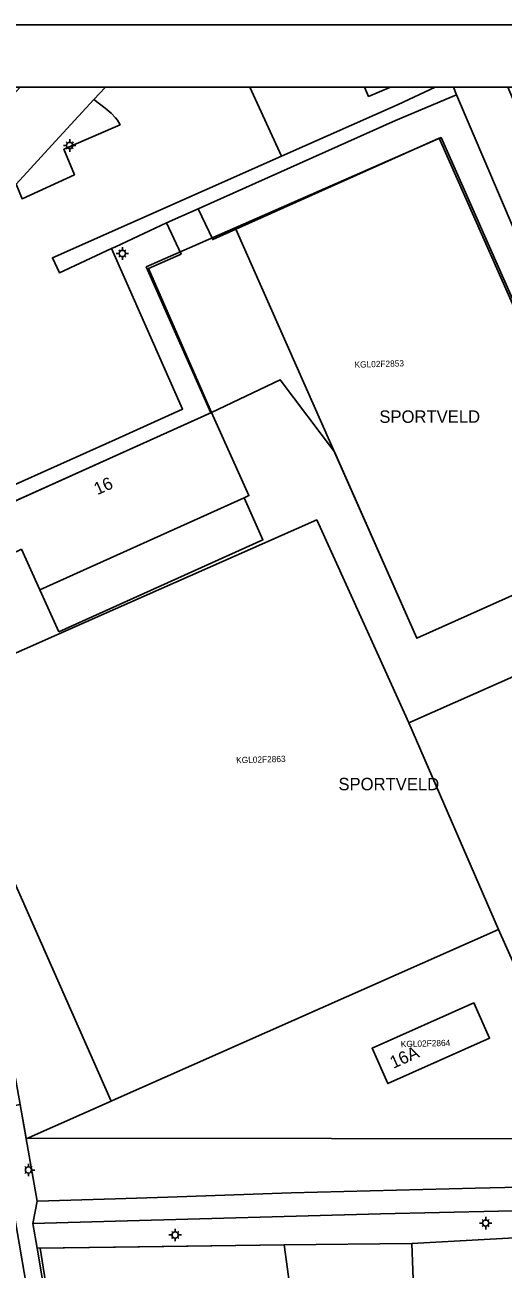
# Model space of a CAD drawing. Extents: x 124901 to 125496, y 515369 to 515789.
# Drawn here: x 124992.7 to 125031.2, y 515689 to 515789 of the extents above; entities that cross this region are included whole.
import ezdxf

# ---------------------------------------------------------------- set-up
doc = ezdxf.new("R2010")
doc.units = 0
for name, color, linetype in [('Alg Kaders', 7, 'Continuous'), ('Gebouw', 7, 'Continuous'), ('Lichtmast', 7, 'Continuous'), ('Luifel', 7, 'Continuous'), ('Onbegroeid terrein', 7, 'Continuous'), ('Parkeren', 7, 'Continuous'), ('Perceelnummers', 7, 'Continuous'), ('Perceelsgrenzen', 7, 'Continuous'), ('Scheiding', 7, 'Continuous'), ('Teksten', 7, 'Continuous'), ('Vegetatie', 7, 'Continuous'), ('Voetpad', 7, 'Continuous'), ('Wegen lokale weg', 7, 'Continuous')]:
    doc.layers.add(name, color=color, linetype=linetype)

msp = doc.modelspace()

# ---------------------------------------------------------------- linework, layer by layer
at = {"layer": 'Alg Kaders'}
for points in [[(125495.93, 515789.04), (124901.43, 515789.04), (124901.43, 515368.54), (125495.93, 515368.54)], [(125490.93, 515784.04), (124906.43, 515784.04), (124906.43, 515373.54), (125490.93, 515373.54)]]:
    msp.add_lwpolyline(points, close=True, dxfattribs=at)
at = {"layer": 'Gebouw'}
for points in [[(124992.44, 515746.88), (124993.92, 515743.59), (125010.35, 515751), (125010.74, 515751.18), (125007.72, 515757.87), (124991.57, 515750.58), (124990.9, 515750.28), (124990.97, 515750.12), (124987.8, 515748.69), (124989.25, 515745.35)], [(125021.91, 515703.88), (125030.1, 515707.53), (125028.83, 515710.37), (125020.64, 515706.72)]]:
    msp.add_lwpolyline(points, close=True, dxfattribs=at)
at = {"layer": 'Lichtmast'}
for p, q in [((124996.03, 515779.35), (124995.83, 515779.34)), ((124996.12, 515779.56), (124996.05, 515779.63)), ((124996.33, 515779.64), (124996.33, 515779.84)), ((124996.54, 515779.56), (124996.61, 515779.63)), ((124996.63, 515779.34), (124996.83, 515779.34)), ((124996.12, 515779.13), (124996.05, 515779.06)), ((124996.33, 515779.04), (124996.33, 515778.84)), ((124996.54, 515779.13), (124996.61, 515779.06)), ((125000.26, 515770.65), (125000.06, 515770.65)), ((125000.35, 515770.86), (125000.28, 515770.93)), ((125000.35, 515770.43), (125000.28, 515770.36)), ((125000.56, 515770.95), (125000.56, 515771.15)), ((125000.56, 515770.35), (125000.56, 515770.15)), ((125000.77, 515770.86), (125000.84, 515770.93)), ((125000.77, 515770.43), (125000.84, 515770.36)), ((125000.86, 515770.65), (125001.06, 515770.65)), ((124992.8, 515697.13), (124992.73, 515697.2)), ((124993.01, 515697.22), (124993.01, 515697.42)), ((124993.23, 515697.13), (124993.3, 515697.2)), ((124992.8, 515696.71), (124992.73, 515696.64)), ((124993.01, 515696.62), (124993.01, 515696.42)), ((124993.23, 515696.71), (124993.3, 515696.64)), ((124993.32, 515696.92), (124993.51, 515696.92)), ((125029.78, 515692.95), (125029.78, 515693.15)), ((125004.81, 515692), (125004.81, 515692.2)), ((125029.48, 515692.65), (125029.28, 515692.65)), ((125029.57, 515692.86), (125029.5, 515692.93)), ((125029.57, 515692.44), (125029.5, 515692.37)), ((125029.78, 515692.35), (125029.78, 515692.15)), ((125029.99, 515692.86), (125030.06, 515692.94)), ((125029.99, 515692.44), (125030.06, 515692.37)), ((125030.08, 515692.65), (125030.28, 515692.65)), ((125004.51, 515691.7), (125004.31, 515691.7)), ((125004.6, 515691.91), (125004.53, 515691.98)), ((125004.6, 515691.49), (125004.53, 515691.42)), ((125004.81, 515691.4), (125004.81, 515691.2)), ((125005.03, 515691.91), (125005.1, 515691.98)), ((125005.03, 515691.49), (125005.1, 515691.42)), ((125005.11, 515691.7), (125005.31, 515691.7))]:
    msp.add_line(p, q, dxfattribs=at)
for centre in [(124996.33, 515779.34), (125000.56, 515770.65), (124993.01, 515696.92), (125029.78, 515692.65), (125004.81, 515691.7)]:
    msp.add_circle(centre, 0.25, dxfattribs=at)
at = {"layer": 'Luifel'}
msp.add_lwpolyline([(124995.44, 515740.22), (125011.87, 515747.63), (125010.35, 515751), (124993.92, 515743.59)], close=True, dxfattribs=at)
at = {"layer": 'Onbegroeid terrein'}
for points in [[(125037.49, 515745.64), (125040.6, 515747.04), (125026.03, 515779.93), (125009.7, 515772.62), (125024.25, 515739.7)], [(125021.18, 515738.22), (125016.2, 515749.22), (125014.57, 515748.5), (125000, 515742.06), (124987.95, 515736.74), (124985.06, 515735.46), (124999.67, 515702.47), (125000, 515702.62), (125030.82, 515716.27), (125023.59, 515732.89)], [(125054.69, 515707.14), (125044.58, 515729.88), (125040.02, 515740.15), (125023.59, 515732.89), (125030.82, 515716.27), (125038.16, 515699.83)]]:
    msp.add_lwpolyline(points, close=True, dxfattribs=at)
for points in [[(124987.95, 515736.74), (125000, 515742.06), (125014.57, 515748.5), (125016.2, 515749.22), (125021.18, 515738.22), (125023.59, 515732.89), (125040.02, 515740.15), (125037.49, 515745.64), (125024.25, 515739.7), (125009.7, 515772.62), (125007.83, 515771.77), (125006.67, 515774.25), (125004.12, 515773.12), (125005.28, 515770.61), (125002.67, 515769.45), (125007.72, 515757.87), (125010.74, 515751.18), (125010.35, 515751), (124993.92, 515743.59), (124992.44, 515746.88)], [(125045.2, 515692.2), (125023.85, 515691.02), (125013.58, 515690.89), (125000, 515690.71), (124993.7, 515690.63), (124996.1, 515676.41)]]:
    msp.add_lwpolyline(points, dxfattribs=at)
at = {"layer": 'Parkeren'}
for points in [[(124991.17, 515751.71), (125000, 515755.69), (125005.41, 515758.13), (125000, 515770.34), (124999.68, 515771.06), (124995.5, 515769.11), (124994.94, 515770.31), (125013.36, 515778.47), (125010.81, 515784.04)], [(124999.2, 515784.04), (124998.28, 515783.04), (124999.19, 515782.34), (124999.67, 515781.95), (125000, 515781.56), (125000.16, 515781.37), (125000.38, 515781.01), (125000, 515780.85), (124995.86, 515779.04), (124996.71, 515776.99), (124992.5, 515775.05)], [(125020.04, 515784.04), (125020.37, 515783.29), (125022.12, 515784.04)]]:
    msp.add_lwpolyline(points, dxfattribs=at)
at = {"layer": 'Perceelsgrenzen'}
for points in [[(124988.91, 515713.21), (124972.89, 515742.59), (124990.9, 515750.28), (125007.67, 515757.84), (125002.48, 515769.57), (125026.19, 515779.98), (125040.83, 515746.88), (125037.56, 515745.5), (125057.1, 515701.64), (125041.95, 515699.43), (124992.82, 515699.48), (124992, 515704.14), (124990.67, 515708.8), (124990.18, 515710.26)], [(125037.56, 515745.5), (125037.49, 515745.64), (125024.25, 515739.7), (125017.62, 515754.7), (125013.26, 515760.5), (125007.72, 515757.87), (125007.67, 515757.84), (125002.48, 515769.57), (125026.19, 515779.98), (125040.83, 515746.88)], [(124972.89, 515742.59), (124988.91, 515713.21), (124990.18, 515710.26), (124990.67, 515708.8), (124992, 515704.14), (124992.82, 515699.48), (125041.95, 515699.43), (125057.1, 515701.64), (125037.56, 515745.5), (125037.49, 515745.64), (125024.25, 515739.7), (125017.62, 515754.7), (125013.26, 515760.5), (125007.72, 515757.87), (125007.67, 515757.84), (124990.9, 515750.28)], [(125021.91, 515703.88), (125020.64, 515706.72), (125028.83, 515710.37), (125030.1, 515707.53)], [(125020.64, 515706.72), (125028.83, 515710.37), (125030.1, 515707.53), (125021.91, 515703.88)], [(125013.58, 515690.89), (125016.35, 515670.5), (125019.58, 515665.25), (125012.95, 515664.36), (125007.84, 515663.65), (124998.6, 515662.33), (124995.81, 515678.94), (124993.95, 515690.63)], [(125040.93, 515627.09), (125037.14, 515630.72), (125036.71, 515631.41), (125031.87, 515639.28), (125034.42, 515641.13), (125026.89, 515653.38), (125023.81, 515658.37), (125019.58, 515665.25), (125016.35, 515670.5), (125013.58, 515690.89), (125023.85, 515691.02), (125024.01, 515686.71), (125031.07, 515680.4), (125080.29, 515636.38), (125072.68, 515622.17), (125060.21, 515633.45), (125055.52, 515628.22), (125053.57, 515626.04), (125048.99, 515620.93), (125048.23, 515620.08), (125048.15, 515620.18), (125046.13, 515622.12)]]:
    msp.add_lwpolyline(points, close=True, dxfattribs=at)
msp.add_lwpolyline([(124995.81, 515678.94), (124993.95, 515690.63), (125013.58, 515690.89), (125023.85, 515691.02), (125024.01, 515686.71)], dxfattribs=at)
at = {"layer": 'Scheiding'}
for points in [[(125009.7, 515772.62), (125026.03, 515779.93), (125040.6, 515747.04), (125037.49, 515745.64)], [(125009.7, 515772.62), (125024.25, 515739.7), (125037.49, 515745.64)], [(125021.18, 515738.22), (125016.2, 515749.22), (125014.57, 515748.5)], [(125000, 515742.06), (125014.57, 515748.5)], [(124987.95, 515736.74), (125000, 515742.06)], [(125040.02, 515740.15), (125023.59, 515732.89)], [(125023.59, 515732.89), (125021.18, 515738.22)], [(124999.67, 515702.47), (124985.06, 515735.46)], [(125030.82, 515716.27), (125023.59, 515732.89)], [(125030.82, 515716.27), (125000, 515702.62)], [(125038.16, 515699.83), (125030.82, 515716.27)]]:
    msp.add_lwpolyline(points, dxfattribs=at)
at = {"layer": 'Vegetatie'}
for points in [[(125041.35, 515750.83), (125027.43, 515783.41), (125022.53, 515781.35), (125006.67, 515774.25), (125007.83, 515771.77), (125009.7, 515772.62), (125026.03, 515779.93), (125040.6, 515747.04)], [(125010.81, 515784.04), (125013.36, 515778.47), (125022.74, 515782.64), (125025.72, 515784.04)], [(125022.12, 515784.04), (125020.37, 515783.29), (125020.04, 515784.04)]]:
    msp.add_lwpolyline(points, dxfattribs=at)
for points in [[(125000, 515780.85), (125000.38, 515781.01), (125000.16, 515781.37), (125000, 515781.56), (124999.67, 515781.95), (124999.19, 515782.34), (124998.28, 515783.04), (124995.19, 515779.7), (124992.03, 515776.24), (124992.5, 515775.05), (124996.71, 515776.99), (124995.86, 515779.04)], [(124991.57, 515750.58), (125007.72, 515757.87), (125002.67, 515769.45), (125005.28, 515770.61), (125004.12, 515773.12), (125000, 515771.2), (124999.68, 515771.06), (125000, 515770.34), (125005.41, 515758.13), (125000, 515755.69), (124991.17, 515751.71), (124991.34, 515751.23)], [(124983.93, 515722.35), (124987.07, 515716.68), (124988.53, 515713.91), (124989.57, 515711.68), (124990.18, 515710.26), (124990.67, 515708.8), (124991.21, 515707.07), (124992, 515704.14), (124992.34, 515702.2), (124992.82, 515699.43), (124999.67, 515702.47), (124985.06, 515735.46), (124983.14, 515739.73), (124976.15, 515736.65)], [(125000, 515694.6), (125004.22, 515694.73), (125014.15, 515695.09), (125028.96, 515695.47), (125040.75, 515695.74), (125042.55, 515695.8), (125043.65, 515695.99), (125045.48, 515696.54), (125051.41, 515698.39), (125057.57, 515700.42), (125054.69, 515707.14), (125038.16, 515699.83), (125030.82, 515716.27), (125000, 515702.62), (124999.67, 515702.47), (124992.82, 515699.43), (124993.71, 515694.42)], [(125021.31, 515693.41), (125000, 515692.81), (124993.36, 515692.63), (124993.7, 515690.63), (125000, 515690.71), (125013.58, 515690.89), (125023.85, 515691.02), (125045.2, 515692.2), (125056.04, 515695.61), (125062.07, 515697.48), (125063.43, 515697.93), (125068.33, 515700.76), (125073.29, 515703.31), (125092.77, 515709.75), (125085.5, 515714.73), (125084.13, 515712.93), (125068.45, 515702.2), (125056.91, 515698.17), (125046.16, 515694.66), (125044.4, 515694.15), (125043.08, 515693.92), (125040.29, 515693.82)], [(125030.1, 515707.53), (125021.91, 515703.88), (125020.64, 515706.72), (125028.83, 515710.37)]]:
    msp.add_lwpolyline(points, close=True, dxfattribs=at)
at = {"layer": 'Voetpad'}
for points in [[(125025.72, 515784.04), (125022.74, 515782.64), (125013.36, 515778.47), (124994.94, 515770.31), (124995.5, 515769.11), (124999.68, 515771.06), (125000, 515771.2), (125004.12, 515773.12), (125006.67, 515774.25), (125022.53, 515781.35), (125027.43, 515783.41), (125027.19, 515784.04)], [(124996.1, 515676.41), (124993.7, 515690.63), (124993.36, 515692.63), (124993.71, 515694.42), (124992.82, 515699.43), (124992.34, 515702.2), (124990.36, 515701.83), (124990.47, 515701.31), (124992.26, 515691.05), (124993.89, 515681.43)], [(125040.75, 515695.74), (125028.96, 515695.47), (125014.15, 515695.09), (125004.22, 515694.73), (125000, 515694.6), (124993.71, 515694.42), (124993.36, 515692.63), (125000, 515692.81), (125021.31, 515693.41), (125040.29, 515693.82)]]:
    msp.add_lwpolyline(points, dxfattribs=at)
at = {"layer": 'Wegen lokale weg'}
for points in [[(124992.33, 515784.04), (124973.7, 515763.83), (124971.42, 515761.34), (124970.98, 515760.86), (124974.75, 515757.46), (124980.04, 515763.18), (124983.95, 515767.44), (124986.86, 515770.61), (124992.03, 515776.24), (124995.19, 515779.7), (124998.28, 515783.04), (124999.2, 515784.04)], [(125027.19, 515784.04), (125027.43, 515783.41), (125041.35, 515750.83), (125041.86, 515749.65), (125049.46, 515732.03), (125049.55, 515732.07), (125049.82, 515731.46), (125055.56, 515735.33), (125046.71, 515748.26), (125051.04, 515751.23), (125049.07, 515754.11), (125045.03, 515752.4), (125044.74, 515753.17), (125036.83, 515771.8), (125031.55, 515784.04)]]:
    msp.add_lwpolyline(points, dxfattribs=at)

# ---------------------------------------------------------------- texts
at = {"layer": 'Perceelnummers'}
for s, rotation, p in [('KGL02F2853', 1.6301, (125019.24, 515761.46)), ('KGL02F2863', 1.63, (125009.72, 515729.64)), ('KGL02F2864', 1.6301, (125022.96, 515706.8))]:
    msp.add_text(s, height=0.5, rotation=rotation, dxfattribs=at).set_placement(p)
at = {"layer": 'Teksten'}
for p in [(125021.23, 515757.03), (125017.94, 515727.47)]:
    msp.add_text('SPORTVELD', height=1, dxfattribs=at).set_placement(p)
for s, rotation, p in [('16', 24.3, (124998.55, 515751.2)), ('16A', 24, (125022.35, 515705.06))]:
    msp.add_text(s, height=1, rotation=rotation, dxfattribs=at).set_placement(p)

doc.saveas('drawing.dxf')
